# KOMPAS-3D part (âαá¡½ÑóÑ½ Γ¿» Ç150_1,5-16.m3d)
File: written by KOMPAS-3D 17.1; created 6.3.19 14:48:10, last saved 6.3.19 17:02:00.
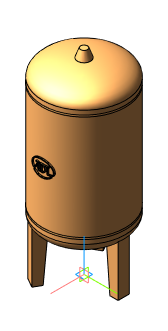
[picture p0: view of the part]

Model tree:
1. Операция без истории:1  (with: Сечение модели:1)

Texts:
  Гранлевел тип А100_1,5-16
  Гранлевел тип А150_1,5-16
  Гранлевел тип А220_1,5-16
  Гранлевел тип А350_1,5-16
  Гранлевел тип А500_1,5-16
  Гранлевел тип А700_1,5-16
  Гранлевел тип А900_1,5-16
  Гранлевел тип А1000_1,5-16
  Гранлевел тип А1400_1,5-16
  Точка начала. Х
  Точка начала. Y
  Точка начала. Z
